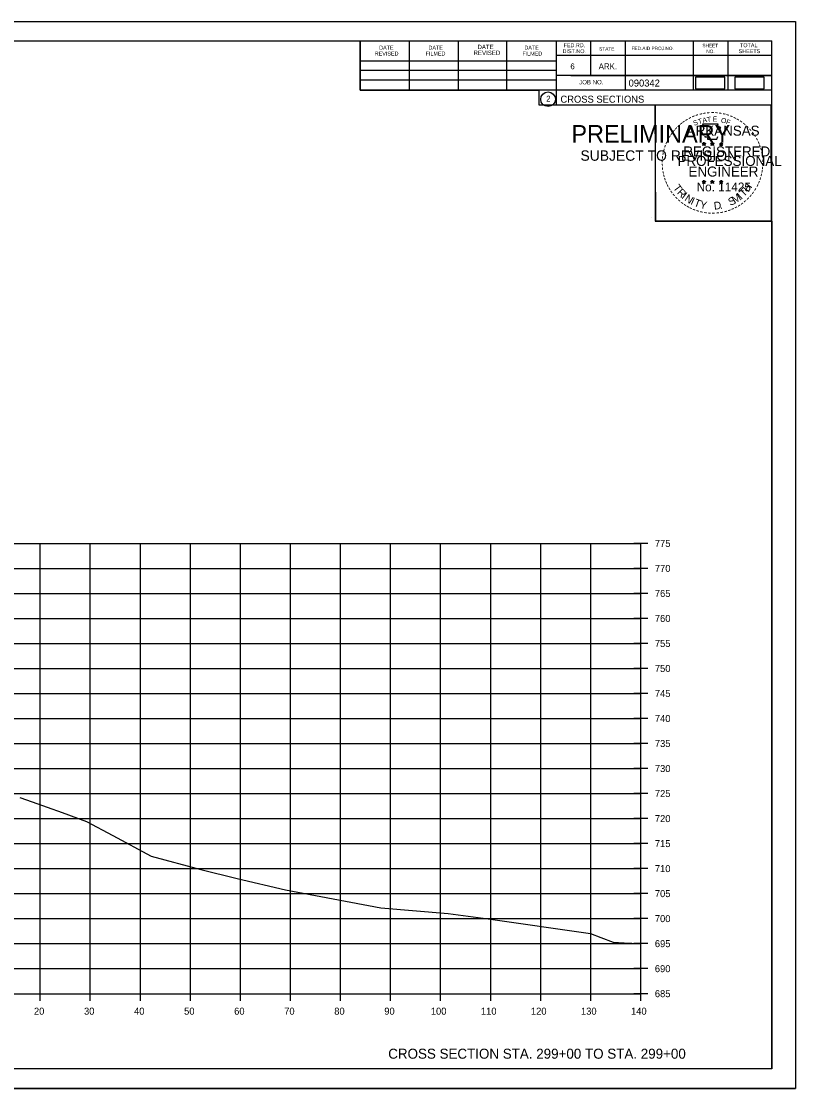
# Model space of a CAD drawing. Extents: x 1370515 to 1370849, y 383299 to 386073.
# Drawn here: x 1370694 to 1370848.7, y 383299.4 to 383512.8 of the extents above; entities that cross this region are included whole.
import ezdxf

# ---------------------------------------------------------------- set-up
doc = ezdxf.new("R2010")
doc.units = 0
for name, color, linetype in [('R_Axis', 7, 'Continuous'), ('R_Axis Annot', 7, 'Continuous'), ('R_Border', 7, 'Continuous'), ('R_Border PE', 7, 'Continuous'), ('R_Border Prem', 7, 'Continuous'), ('R_Detour', 7, 'Continuous'), ('R_Draft', 7, 'Continuous'), ('R_Exist Surface', 7, 'Continuous'), ('R_Grid', 7, 'Continuous'), ('R_No Plot', 7, 'Continuous')]:
    doc.layers.add(name, color=color, linetype=linetype)

msp = doc.modelspace()

# ---------------------------------------------------------------- linework, layer by layer
at = {"layer": 'R_Axis'}
for p, q in [((1370819.2, 383408.41), (1370816.4, 383408.41)), ((1370817.8, 383318.41), (1370817.8, 383408.41)), ((1370819.2, 383403.41), (1370816.4, 383403.41)), ((1370819.2, 383398.41), (1370816.4, 383398.41)), ((1370819.2, 383393.41), (1370816.4, 383393.41)), ((1370819.2, 383388.41), (1370816.4, 383388.41)), ((1370819.2, 383383.41), (1370816.4, 383383.41)), ((1370819.2, 383378.41), (1370816.4, 383378.41)), ((1370819.2, 383373.41), (1370816.4, 383373.41)), ((1370819.2, 383368.41), (1370816.4, 383368.41)), ((1370819.2, 383363.41), (1370816.4, 383363.41)), ((1370819.2, 383358.41), (1370816.4, 383358.41)), ((1370819.2, 383353.41), (1370816.4, 383353.41)), ((1370819.2, 383348.41), (1370816.4, 383348.41)), ((1370819.2, 383343.41), (1370816.4, 383343.41)), ((1370819.2, 383338.41), (1370816.4, 383338.41)), ((1370819.2, 383333.41), (1370816.4, 383333.41)), ((1370819.2, 383328.41), (1370816.4, 383328.41)), ((1370819.2, 383323.41), (1370816.4, 383323.41)), ((1370697.8, 383317.01), (1370697.8, 383319.81)), ((1370707.8, 383317.01), (1370707.8, 383319.81)), ((1370717.8, 383317.01), (1370717.8, 383319.81)), ((1370727.8, 383317.01), (1370727.8, 383319.81)), ((1370737.8, 383317.01), (1370737.8, 383319.81)), ((1370747.8, 383317.01), (1370747.8, 383319.81)), ((1370757.8, 383317.01), (1370757.8, 383319.81)), ((1370767.8, 383317.01), (1370767.8, 383319.81)), ((1370777.8, 383317.01), (1370777.8, 383319.81)), ((1370787.8, 383317.01), (1370787.8, 383319.81)), ((1370797.8, 383317.01), (1370797.8, 383319.81)), ((1370807.8, 383317.01), (1370807.8, 383319.81)), ((1370817.8, 383317.01), (1370817.8, 383319.81)), ((1370537.8, 383318.41), (1370817.8, 383318.41)), ((1370819.2, 383318.41), (1370816.4, 383318.41))]:
    msp.add_line(p, q, dxfattribs=at)
at = {"layer": 'R_Border'}
for p, q in [((1370527.8, 383508.87), (1370843.98, 383508.87)), ((1370761.72, 383498.99), (1370761.72, 383508.87)), ((1370771.58, 383498.99), (1370771.58, 383508.67)), ((1370781.34, 383498.99), (1370781.34, 383508.67)), ((1370791.02, 383498.99), (1370791.02, 383508.67)), ((1370800.88, 383508.87), (1370800.88, 383496.07)), ((1370807.72, 383508.87), (1370807.72, 383501.93)), ((1370814.66, 383508.87), (1370814.66, 383498.99)), ((1370828.24, 383508.87), (1370828.24, 383498.99)), ((1370835.18, 383508.87), (1370835.18, 383498.99)), ((1370843.98, 383303.41), (1370843.98, 383508.87)), ((1370761.72, 383504.85), (1370800.88, 383504.85)), ((1370843.98, 383505.93), (1370800.88, 383505.93)), ((1370843.98, 383505.95), (1370843.98, 383505.95)), ((1370761.72, 383502.99), (1370800.88, 383502.99)), ((1370761.72, 383498.99), (1370761.72, 383501.05)), ((1370761.72, 383501.05), (1370800.88, 383501.05)), ((1370843.98, 383501.93), (1370800.88, 383501.93)), ((1370803.84, 383501.93), (1370843.98, 383501.93)), ((1370843.98, 383498.99), (1370761.72, 383498.99)), ((1370800.88, 383496.07), (1370843.98, 383496.07)), ((1370843.98, 383303.41), (1370527.8, 383303.41))]:
    msp.add_line(p, q, dxfattribs=at)
msp.add_circle((1370799.27, 383497.2), 1.47, dxfattribs=at)
at = {"layer": 'R_Border PE'}
for p, q in [((1370830.07, 383488.32), (1370830.42, 383488.21)), ((1370830.07, 383488.32), (1370830.32, 383488.28)), ((1370830.07, 383488.32), (1370830.3, 383488.2)), ((1370830.2, 383487.92), (1370830.42, 383488.21)), ((1370830.2, 383487.92), (1370830.33, 383488.16)), ((1370830.2, 383487.92), (1370830.41, 383488.13)), ((1370830.42, 383488.58), (1370830.37, 383488.33)), ((1370830.63, 383487.92), (1370830.41, 383488.13)), ((1370830.42, 383488.21), (1370830.42, 383488.58)), ((1370830.42, 383488.58), (1370830.46, 383488.33)), ((1370830.76, 383488.32), (1370830.42, 383488.21)), ((1370830.63, 383487.92), (1370830.42, 383488.21)), ((1370830.76, 383488.32), (1370830.48, 383488.27)), ((1370830.63, 383487.92), (1370830.49, 383488.21)), ((1370830.76, 383488.32), (1370830.56, 383488.22)), ((1370831.74, 383488.32), (1370832.09, 383488.21)), ((1370831.74, 383488.32), (1370831.99, 383488.28)), ((1370831.74, 383488.32), (1370831.97, 383488.2)), ((1370831.87, 383487.92), (1370832.09, 383488.21)), ((1370831.87, 383487.92), (1370832, 383488.16)), ((1370831.87, 383487.92), (1370832.08, 383488.13)), ((1370832.09, 383488.58), (1370832.04, 383488.33)), ((1370832.3, 383487.92), (1370832.08, 383488.13)), ((1370832.09, 383488.21), (1370832.09, 383488.58)), ((1370832.09, 383488.58), (1370832.13, 383488.33)), ((1370832.43, 383488.32), (1370832.09, 383488.21)), ((1370832.3, 383487.92), (1370832.09, 383488.21)), ((1370832.43, 383488.32), (1370832.15, 383488.27)), ((1370832.3, 383487.92), (1370832.16, 383488.21)), ((1370832.43, 383488.32), (1370832.23, 383488.22)), ((1370833.5, 383488.31), (1370833.85, 383488.2)), ((1370833.5, 383488.31), (1370833.75, 383488.27)), ((1370833.5, 383488.31), (1370833.74, 383488.19)), ((1370833.63, 383487.9), (1370833.85, 383488.2)), ((1370833.63, 383487.9), (1370833.76, 383488.15)), ((1370833.63, 383487.9), (1370833.85, 383488.12)), ((1370833.85, 383488.57), (1370833.81, 383488.31)), ((1370833.85, 383488.2), (1370833.85, 383488.57)), ((1370833.85, 383488.57), (1370833.9, 383488.32)), ((1370834.2, 383488.31), (1370833.85, 383488.2)), ((1370834.06, 383487.9), (1370833.85, 383488.2)), ((1370834.06, 383487.9), (1370833.85, 383488.12)), ((1370834.2, 383488.31), (1370833.91, 383488.26)), ((1370834.06, 383487.9), (1370833.93, 383488.19)), ((1370834.2, 383488.31), (1370833.99, 383488.21)), ((1370830.06, 383480.75), (1370830.41, 383480.64)), ((1370830.06, 383480.75), (1370830.32, 383480.71)), ((1370830.06, 383480.75), (1370830.3, 383480.63)), ((1370830.41, 383481), (1370830.37, 383480.75)), ((1370830.41, 383480.64), (1370830.41, 383481)), ((1370830.41, 383481), (1370830.46, 383480.75)), ((1370830.76, 383480.75), (1370830.41, 383480.64)), ((1370830.76, 383480.75), (1370830.47, 383480.7)), ((1370830.76, 383480.75), (1370830.55, 383480.65)), ((1370831.73, 383480.75), (1370832.08, 383480.64)), ((1370831.73, 383480.75), (1370831.98, 383480.71)), ((1370831.73, 383480.75), (1370831.97, 383480.63)), ((1370832.08, 383481), (1370832.04, 383480.75)), ((1370832.08, 383480.64), (1370832.08, 383481)), ((1370832.08, 383481), (1370832.13, 383480.75)), ((1370832.43, 383480.75), (1370832.08, 383480.64)), ((1370832.43, 383480.75), (1370832.14, 383480.7)), ((1370832.43, 383480.75), (1370832.22, 383480.65)), ((1370833.5, 383480.74), (1370833.85, 383480.63)), ((1370833.5, 383480.74), (1370833.75, 383480.7)), ((1370833.5, 383480.74), (1370833.74, 383480.62)), ((1370833.85, 383480.99), (1370833.81, 383480.74)), ((1370833.85, 383480.63), (1370833.85, 383480.99)), ((1370833.85, 383480.99), (1370833.9, 383480.74)), ((1370834.19, 383480.74), (1370833.85, 383480.63)), ((1370834.19, 383480.74), (1370833.91, 383480.69)), ((1370834.19, 383480.74), (1370833.99, 383480.64)), ((1370830.2, 383480.34), (1370830.41, 383480.64)), ((1370830.2, 383480.34), (1370830.32, 383480.59)), ((1370830.2, 383480.34), (1370830.41, 383480.56)), ((1370830.62, 383480.34), (1370830.41, 383480.64)), ((1370830.62, 383480.34), (1370830.41, 383480.56)), ((1370830.62, 383480.34), (1370830.49, 383480.63)), ((1370831.86, 383480.34), (1370832.08, 383480.64)), ((1370831.86, 383480.34), (1370831.99, 383480.59)), ((1370831.86, 383480.34), (1370832.08, 383480.56)), ((1370832.29, 383480.34), (1370832.08, 383480.64)), ((1370832.29, 383480.34), (1370832.08, 383480.56)), ((1370832.29, 383480.34), (1370832.16, 383480.63)), ((1370833.63, 383480.33), (1370833.85, 383480.63)), ((1370833.63, 383480.33), (1370833.76, 383480.58)), ((1370833.63, 383480.33), (1370833.85, 383480.55)), ((1370834.06, 383480.33), (1370833.85, 383480.63)), ((1370834.06, 383480.33), (1370833.85, 383480.55)), ((1370834.06, 383480.33), (1370833.92, 383480.62))]:
    msp.add_line(p, q, dxfattribs=at)
for points in [[(1370830.11, 383492.2), (1370830.38, 383491.37)], [(1370833.62, 383491.28), (1370833.76, 383491.56), (1370833.08, 383491.54), (1370833.22, 383492.2), (1370830.11, 383492.2)], [(1370830.6, 383489.78), (1370830.6, 383489.69), (1370831.16, 383489.67), (1370831.11, 383489.2), (1370832.98, 383489.2), (1370833.18, 383489.74)], [(1370830.42, 383488.58), (1370830.63, 383487.92), (1370830.07, 383488.32), (1370830.76, 383488.32), (1370830.2, 383487.92), (1370830.42, 383488.58)], [(1370832.09, 383488.58), (1370832.3, 383487.92), (1370831.74, 383488.32), (1370832.43, 383488.32), (1370831.87, 383487.92), (1370832.09, 383488.58)], [(1370833.85, 383488.57), (1370834.06, 383487.9), (1370833.5, 383488.31), (1370834.2, 383488.31), (1370833.63, 383487.9), (1370833.85, 383488.57)], [(1370830.41, 383481), (1370830.62, 383480.34), (1370830.06, 383480.75), (1370830.76, 383480.75), (1370830.2, 383480.34), (1370830.41, 383481)], [(1370832.08, 383481), (1370832.29, 383480.34), (1370831.73, 383480.75), (1370832.43, 383480.75), (1370831.86, 383480.34), (1370832.08, 383481)], [(1370833.85, 383480.99), (1370834.06, 383480.33), (1370833.5, 383480.74), (1370834.19, 383480.74), (1370833.63, 383480.33), (1370833.85, 383480.99)]]:
    msp.add_lwpolyline(points, dxfattribs=at)
for centre, radius in [((1370830.41, 383488.21), 0.172), ((1370830.41, 383488.21), 0.145), ((1370830.41, 383488.21), 0.116), ((1370830.41, 383488.21), 0.0991), ((1370830.41, 383488.21), 0.0747), ((1370830.41, 383488.21), 0.0495), ((1370830.41, 383488.21), 0.0296), ((1370832.08, 383488.21), 0.172), ((1370832.08, 383488.21), 0.145), ((1370832.08, 383488.21), 0.116), ((1370832.08, 383488.21), 0.0991), ((1370832.08, 383488.21), 0.0747), ((1370832.08, 383488.21), 0.0495), ((1370832.08, 383488.21), 0.0296), ((1370833.85, 383488.2), 0.172), ((1370833.85, 383488.2), 0.145), ((1370833.85, 383488.2), 0.116), ((1370833.85, 383488.2), 0.0991), ((1370833.85, 383488.2), 0.0747), ((1370833.85, 383488.2), 0.0495), ((1370833.85, 383488.2), 0.0296), ((1370830.41, 383480.64), 0.172), ((1370830.41, 383480.64), 0.145), ((1370830.41, 383480.64), 0.116), ((1370830.41, 383480.64), 0.0991), ((1370832.08, 383480.64), 0.172), ((1370832.08, 383480.64), 0.145), ((1370832.08, 383480.64), 0.116), ((1370832.08, 383480.64), 0.0991), ((1370833.85, 383480.63), 0.172), ((1370833.85, 383480.63), 0.145), ((1370833.85, 383480.63), 0.116), ((1370830.41, 383480.64), 0.0747), ((1370830.41, 383480.64), 0.0495), ((1370830.41, 383480.64), 0.0296), ((1370832.08, 383480.64), 0.0747), ((1370832.08, 383480.64), 0.0495), ((1370832.08, 383480.64), 0.0296), ((1370833.85, 383480.63), 0.0991), ((1370833.85, 383480.63), 0.0747), ((1370833.85, 383480.63), 0.0495), ((1370833.85, 383480.63), 0.0296)]:
    msp.add_circle(centre, radius, dxfattribs=at)
at = {"layer": 'R_Detour'}
for points in [[(1370828.73, 383499.29), (1370834.56, 383499.29), (1370834.56, 383501.6), (1370828.73, 383501.6)], [(1370836.58, 383499.29), (1370842.42, 383499.29), (1370842.42, 383501.6), (1370836.58, 383501.6)]]:
    msp.add_lwpolyline(points, close=True, dxfattribs=at)
at = {"layer": 'R_Exist Surface'}
msp.add_lwpolyline([(1370693.73, 383357.63), (1370696.19, 383356.74), (1370702.16, 383354.62), (1370707.02, 383352.84), (1370712.31, 383350.04), (1370719.94, 383345.87), (1370729.9, 383343.26), (1370737.12, 383341.41), (1370746.83, 383339.15), (1370765.85, 383335.57), (1370779.33, 383334.42), (1370787.28, 383333.37), (1370807.73, 383330.45), (1370809.79, 383329.63), (1370812.27, 383328.73), (1370814.48, 383328.6), (1370817.51, 383328.46), (1370817.8, 383328.55)], dxfattribs=at)
at = {"layer": 'R_Grid'}
for p, q in [((1370537.8, 383408.41), (1370817.8, 383408.41)), ((1370697.8, 383318.41), (1370697.8, 383408.41)), ((1370707.8, 383318.41), (1370707.8, 383408.41)), ((1370717.8, 383318.41), (1370717.8, 383408.41)), ((1370727.8, 383318.41), (1370727.8, 383408.41)), ((1370737.8, 383318.41), (1370737.8, 383408.41)), ((1370747.8, 383318.41), (1370747.8, 383408.41)), ((1370757.8, 383318.41), (1370757.8, 383408.41)), ((1370767.8, 383318.41), (1370767.8, 383408.41)), ((1370777.8, 383318.41), (1370777.8, 383408.41)), ((1370787.8, 383318.41), (1370787.8, 383408.41)), ((1370797.8, 383318.41), (1370797.8, 383408.41)), ((1370807.8, 383318.41), (1370807.8, 383408.41)), ((1370817.8, 383318.41), (1370817.8, 383408.41)), ((1370537.8, 383403.41), (1370817.8, 383403.41)), ((1370537.8, 383398.41), (1370817.8, 383398.41)), ((1370537.8, 383393.41), (1370817.8, 383393.41)), ((1370537.8, 383388.41), (1370817.8, 383388.41)), ((1370537.8, 383383.41), (1370817.8, 383383.41)), ((1370537.8, 383378.41), (1370817.8, 383378.41)), ((1370537.8, 383373.41), (1370817.8, 383373.41)), ((1370537.8, 383368.41), (1370817.8, 383368.41)), ((1370537.8, 383363.41), (1370817.8, 383363.41)), ((1370537.8, 383358.41), (1370817.8, 383358.41)), ((1370537.8, 383353.41), (1370817.8, 383353.41)), ((1370537.8, 383348.41), (1370817.8, 383348.41)), ((1370537.8, 383343.41), (1370817.8, 383343.41)), ((1370537.8, 383338.41), (1370817.8, 383338.41)), ((1370537.8, 383333.41), (1370817.8, 383333.41)), ((1370537.8, 383328.41), (1370817.8, 383328.41)), ((1370537.8, 383323.41), (1370817.8, 383323.41)), ((1370537.8, 383318.41), (1370817.8, 383318.41))]:
    msp.add_line(p, q, dxfattribs=at)
at = {"layer": 'R_No Plot'}
for p, q in [((1370515.4, 383512.76), (1370848.73, 383512.76)), ((1370820.02, 383473.61), (1370820.02, 383473.61)), ((1370515.4, 383299.43), (1370848.73, 383299.43))]:
    msp.add_line(p, q, dxfattribs=at)
for points in [[(1370515.39, 383512.76), (1370848.73, 383512.76), (1370848.73, 383299.43), (1370515.39, 383299.43)], [(1370761.72, 383508.87), (1370761.72, 383498.99), (1370797.45, 383498.99), (1370797.45, 383496.07), (1370820.65, 383496.07), (1370820.65, 383472.85), (1370843.98, 383472.85), (1370843.98, 383303.41), (1370527.8, 383303.41), (1370527.8, 383508.87)], [(1370820.65, 383496.1), (1370843.75, 383496.1), (1370843.87, 383472.85), (1370820.77, 383472.85)]]:
    msp.add_lwpolyline(points, close=True, dxfattribs=at)

# ---------------------------------------------------------------- texts
at = {"layer": 'R_Axis Annot'}
for s, p in [('775', (1370820.6, 383407.71)), ('770', (1370820.6, 383402.71)), ('765', (1370820.6, 383397.71)), ('760', (1370820.6, 383392.71)), ('755', (1370820.6, 383387.71)), ('750', (1370820.6, 383382.71)), ('745', (1370820.6, 383377.71)), ('740', (1370820.6, 383372.71)), ('735', (1370820.6, 383367.71)), ('730', (1370820.6, 383362.71)), ('725', (1370820.6, 383357.71)), ('720', (1370820.6, 383352.71)), ('715', (1370820.6, 383347.71)), ('710', (1370820.6, 383342.71)), ('705', (1370820.6, 383337.71)), ('700', (1370820.6, 383332.71)), ('695', (1370820.6, 383327.71)), ('690', (1370820.6, 383322.71)), ('685', (1370820.6, 383317.71)), ('20', (1370696.54, 383314.21)), ('30', (1370706.54, 383314.21)), ('40', (1370716.54, 383314.21)), ('50', (1370726.54, 383314.21)), ('60', (1370736.54, 383314.21)), ('70', (1370746.54, 383314.21)), ('80', (1370756.54, 383314.21)), ('90', (1370766.54, 383314.21)), ('100', (1370775.84, 383314.21)), ('110', (1370785.84, 383314.21)), ('120', (1370795.84, 383314.21)), ('130', (1370805.84, 383314.21)), ('140', (1370815.84, 383314.21))]:
    msp.add_text(s, height=1.4, dxfattribs=at).set_placement(p)
at = {"layer": 'R_Border'}
for s, height, p in [('REVISED', 0.782, (1370764.64, 383505.93)), ('DATE', 0.782, (1370765.52, 383507.11)), ('FILMED', 0.782, (1370774.8, 383505.93)), ('DATE', 0.782, (1370775.38, 383507.11)), ('REVISED', 0.879, (1370784.38, 383506.03)), ('DATE', 0.879, (1370785.16, 383507.21)), ('FILMED', 0.782, (1370794.14, 383505.93)), ('DATE', 0.782, (1370794.54, 383507.11)), ('DIST.NO.', 0.782, (1370802.16, 383506.41)), ('FED.RD.', 0.782, (1370802.36, 383507.59)), ('STATE', 0.684, (1370809.48, 383506.91)), ('FED.AID PROJ.NO.', 0.684, (1370815.94, 383507.01)), ('SHEET', 0.684, (1370830.1, 383507.59)), ('NO.', 0.684, (1370830.88, 383506.41)), ('SHEETS', 0.782, (1370837.34, 383506.41)), ('TOTAL', 0.782, (1370837.62, 383507.59)), ('6', 1.17, (1370803.72, 383503.19)), ('ARK.', 1.172, (1370809.38, 383503.19)), ('JOB NO.', 0.879, (1370805.48, 383500.17)), ('090342', 1.4, (1370815.36, 383499.73)), ('2', 1.17, (1370798.89, 383496.72)), ('CROSS SECTIONS', 1.4, (1370801.74, 383496.5))]:
    msp.add_text(s, height=height, rotation=360, dxfattribs=at).set_placement(p)
at = {"layer": 'R_Border PE'}
for s, height, rotation, p in [('-', 1.6, 28.7918, (1370827.59, 383492.74)), ('-', 1.6, 24.3072, (1370828.22, 383493.06)), ('-', 1.6, 19.1761, (1370828.86, 383493.33)), ('-', 1.6, 13.6301, (1370829.61, 383493.57)), ('A', 1, 11.2132, (1370830.2, 383492.46)), ('-', 1.6, 10.2193, (1370830.28, 383493.73)), ('T', 1, 6.0228, (1370831.05, 383492.63)), ('-', 1.6, 5.8968, (1370831.01, 383493.84)), ('-', 1.6, 0.1862, (1370831.78, 383493.91)), ('E', 1, 0.8323, (1370832.16, 383492.74)), ('-', 1.6, 357.743, (1370832.51, 383493.9)), ('-', 1.6, 352.1617, (1370833.25, 383493.84)), ('-', 1.6, 347.2049, (1370833.97, 383493.73)), ('-', 1.6, 342.3362, (1370834.61, 383493.58)), ('-', 1.6, 337.8551, (1370835.34, 383493.35)), ('-', 1.6, 334.1211, (1370835.97, 383493.08)), ('-', 1.6, 48.423, (1370825.06, 383490.7)), ('-', 1.6, 42.9622, (1370825.5, 383491.18)), ('-', 1.6, 38.9507, (1370825.94, 383491.6)), ('-', 1.6, 36.2317, (1370826.41, 383491.98)), ('-', 1.6, 34.0636, (1370826.99, 383492.37)), ('ARKANSAS', 2, 360, (1370826.96, 383489.91)), ('S', 1, 21.594, (1370828.46, 383491.88)), ('T', 1, 16.4036, (1370829.38, 383492.21)), ('O', 1, 350.4515, (1370833.76, 383492.53)), ('F', 1, 340.0707, (1370834.71, 383492.3)), ('-', 1.6, 329.6409, (1370836.55, 383492.8)), ('-', 1.6, 325.8627, (1370837.19, 383492.44)), ('-', 1.6, 320.5297, (1370837.8, 383492.01)), ('-', 1.6, 315.5786, (1370838.4, 383491.52)), ('-', 1.6, 62.8713, (1370823.6, 383488.51)), ('-', 1.6, 58.0706, (1370823.92, 383489.12)), ('-', 1.6, 54.2325, (1370824.24, 383489.65)), ('-', 1.6, 50.6142, (1370824.65, 383490.22)), ('-', 1.6, 309.8797, (1370838.97, 383490.97)), ('-', 1.6, 306.6522, (1370839.5, 383490.37)), ('-', 1.4, 303.6753, (1370839.98, 383489.8)), ('-', 1.6, 299.6684, (1370840.3, 383489.2)), ('-', 1.6, 75.461, (1370822.93, 383486.56)), ('-', 1.6, 72.3945, (1370823.12, 383487.27)), ('-', 1.6, 67.7743, (1370823.34, 383487.9)), ('REGISTERED', 2, 360, (1370826.28, 383485.76)), ('DWB', 0.01, 360, (1370830.4, 383488.21)), ('DWB', 0.01, 360, (1370832.07, 383488.21)), ('DWB', 0.01, 360, (1370833.84, 383488.2)), ('-', 1.6, 294.6628, (1370840.63, 383488.58)), ('-', 1.6, 290.5728, (1370840.88, 383488.01)), ('-', 1.6, 285.1233, (1370841.12, 383487.43)), ('-', 1.6, 89.0622, (1370822.69, 383484.45)), ('-', 1.6, 85.1863, (1370822.72, 383485.15)), ('-', 1.6, 81.2013, (1370822.8, 383485.84)), ('PROFESSIONAL', 2, 360, (1370825.13, 383483.86)), ('-', 1.6, 280.5493, (1370841.32, 383486.69)), ('-', 1.6, 276.5962, (1370841.48, 383485.92)), ('-', 1.6, 274.3301, (1370841.54, 383485.2)), ('-', 1.6, 94.1959, (1370822.73, 383483.73)), ('-', 1.6, 98.9479, (1370822.8, 383483.06)), ('ENGINEER', 2, 360, (1370827.32, 383481.74)), ('-', 1.6, 260.9953, (1370841.48, 383483.24)), ('-', 1.6, 263.5172, (1370841.55, 383483.9)), ('-', 1.6, 269.9407, (1370841.57, 383484.56)), ('-', 1.6, 101.7149, (1370822.94, 383482.33)), ('-', 1.6, 105.4578, (1370823.1, 383481.73)), ('-', 1.6, 109.0874, (1370823.31, 383481.1)), ('-', 1.6, 114.0643, (1370823.57, 383480.5)), ('-', 1.6, 247.8887, (1370840.97, 383481.17)), ('-', 1.6, 252.8681, (1370841.19, 383481.85)), ('-', 1.6, 255.7626, (1370841.37, 383482.57)), ('-', 1.6, 115.7288, (1370823.87, 383479.89)), ('-', 1.6, 120.4471, (1370824.23, 383479.3)), ('-', 1.6, 125.8934, (1370824.63, 383478.74)), ('T', 1.54, 306.0406, (1370824.17, 383479.48)), ('R', 1.54, 314.005, (1370824.93, 383478.43)), ('No. 11425', 1.757, 360, (1370828.95, 383478.78)), ('DWB', 0.01, 360, (1370830.4, 383480.63)), ('DWB', 0.01, 360, (1370832.07, 383480.64)), ('DWB', 0.01, 360, (1370833.83, 383480.63)), ('T', 1.54, 46.6444, (1370838.4, 383477.57)), ('H', 1.54, 54.6088, (1370839.29, 383478.51)), ('-', 1.6, 233.8452, (1370839.91, 383479.14)), ('-', 1.6, 239.0712, (1370840.31, 383479.79)), ('-', 1.6, 244.6197, (1370840.71, 383480.54)), ('-', 1.6, 130.7181, (1370825.09, 383478.19)), ('-', 1.6, 134.2238, (1370825.61, 383477.64)), ('-', 1.6, 138.9338, (1370826.14, 383477.18)), ('-', 1.6, 144.6463, (1370826.69, 383476.77)), ('I', 1.54, 321.9694, (1370825.83, 383477.5)), ('N', 1.54, 326.5002, (1370826.4, 383477.03)), ('I', 1.54, 335.3603, (1370827.61, 383476.24)), ('T', 1.54, 339.8912, (1370828.27, 383475.91)), ('Y', 1.54, 347.8556, (1370829.49, 383475.47)), ('D', 1.54, 6.3969, (1370832.47, 383475.11)), ('S', 1.54, 26.9312, (1370835.72, 383475.84)), ('M', 1.54, 32.6563, (1370836.56, 383476.25)), ('I', 1.54, 42.1136, (1370837.84, 383477.09)), ('-', 1.6, 215.7363, (1370837.93, 383477.03)), ('-', 1.6, 221.0851, (1370838.48, 383477.5)), ('-', 1.6, 225.7653, (1370839, 383478.01)), ('-', 1.6, 231.2538, (1370839.48, 383478.57)), ('-', 1.6, 148.0898, (1370827.25, 383476.4)), ('-', 1.6, 151.5704, (1370827.83, 383476.08)), ('-', 1.6, 154.6002, (1370828.35, 383475.83)), ('-', 1.6, 158.5612, (1370828.98, 383475.57)), ('-', 1.6, 162.7983, (1370829.67, 383475.36)), ('-', 1.6, 167.5555, (1370830.38, 383475.2)), ('-', 1.6, 173.1155, (1370831.15, 383475.09)), ('-', 1.6, 176.5183, (1370831.9, 383475.03)), ('-', 1.6, 181.5918, (1370832.64, 383475.05)), ('-', 1.6, 185.8167, (1370833.45, 383475.13)), ('-', 1.6, 191.2858, (1370834.19, 383475.26)), ('.', 1.54, 13.7642, (1370833.66, 383475.24)), ('-', 1.6, 195.4743, (1370834.92, 383475.46)), ('-', 1.6, 200.7184, (1370835.6, 383475.7)), ('-', 1.6, 204.2516, (1370836.21, 383475.98)), ('-', 1.6, 207.3568, (1370836.84, 383476.29)), ('-', 1.6, 212.2491, (1370837.4, 383476.64))]:
    msp.add_text(s, height=height, rotation=rotation, dxfattribs=at).set_placement(p)
at = {"layer": 'R_Border Prem'}
for s, height, p in [('PRELIMINARY', 3.5, (1370803.93, 383488.53)), ('DWB', 0.01, (1370804.68, 383490.38)), ('SUBJECT TO REVISION', 2.0751, (1370805.74, 383484.9))]:
    msp.add_text(s, height=height, rotation=360, dxfattribs=at).set_placement(p)
at = {"layer": 'R_Draft'}
msp.add_text('CROSS SECTION STA. 299+00 TO STA. 299+00', height=2, dxfattribs=at).set_placement((1370767.33, 383305.41))
at = {"layer": 'R_No Plot'}
for p in [(1370696.15, 383356.69), (1370706.97, 383352.79), (1370719.89, 383345.82), (1370737.08, 383341.36), (1370779.29, 383334.37), (1370807.69, 383330.4), (1370812.23, 383328.68), (1370817.47, 383328.41)]:
    msp.add_text('+', height=0.1, dxfattribs=at).set_placement(p)

doc.saveas('drawing.dxf')
